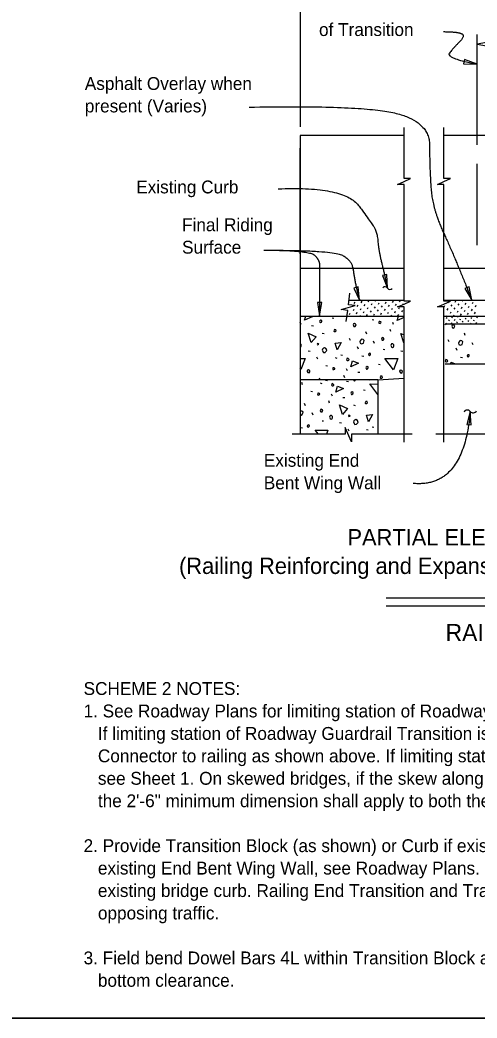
# Model space of a CAD drawing. Extents: x 0 to 41.1, y 0 to 26.
# Drawn here: x 20.53 to 27.71, y 0 to 15.65 of the extents above; entities that cross this region are included whole.
import ezdxf

# ---------------------------------------------------------------- set-up
doc = ezdxf.new("R2010")
doc.units = 0
for name, color, linetype in [('Dimension', 7, 'Continuous'), ('Miscellaneous', 7, 'Continuous'), ('Miscellaneous1', 7, 'Continuous'), ('TrafBarrierConc', 7, 'Continuous')]:
    doc.layers.add(name, color=color, linetype=linetype)

msp = doc.modelspace()

# ---------------------------------------------------------------- linework, layer by layer
at = {"layer": 'Dimension'}
for p, q in [((24.93, 19.167), (24.93, 13.975)), ((27.706, 13.69), (27.706, 15.42)), ((28.887, 6.585), (26.28, 6.585)), ((28.887, 6.46), (26.28, 6.46))]:
    msp.add_line(p, q, dxfattribs=at)
for points in [[(0, 0), (41.067, 0), (41.067, 25.97), (0, 25.97)], [(27.706, 15.271), (27.914, 15.236), (27.914, 15.307)], [(27.706, 14.955), (27.509, 15.031), (27.495, 14.962)], [(26.299, 11.446), (26.292, 11.657), (26.223, 11.643)], [(25.864, 11.257), (25.839, 11.467), (25.772, 11.447)], [(27.623, 11.259), (27.58, 11.466), (27.514, 11.44)], [(25.236, 11.012), (25.271, 11.22), (25.201, 11.22)], [(27.6, 9.513), (27.543, 9.309), (27.613, 9.302)]]:
    msp.add_lwpolyline(points, close=True, dxfattribs=at)
for points in [[(26.561, 12.221), (26.561, 13.073), (26.457, 13.073), (26.561, 13.118), (26.664, 13.163), (26.561, 13.163), (26.561, 13.966)], [(27.186, 12.221), (27.186, 13.073), (27.083, 13.073), (27.186, 13.118), (27.289, 13.163), (27.186, 13.163), (27.186, 13.966)], [(26.561, 9.028), (26.561, 11.151), (26.457, 11.151), (26.561, 11.196), (26.664, 11.241), (26.561, 11.241), (26.561, 12.221)], [(27.186, 9.028), (27.186, 11.151), (27.083, 11.151), (27.186, 11.196), (27.289, 11.241), (27.186, 11.241), (27.186, 12.221)], [(25.653, 10.922), (25.676, 11.096), (25.574, 11.109), (25.682, 11.14), (25.791, 11.171), (25.688, 11.185), (25.712, 11.367)], [(26.686, 9.153), (25.738, 9.153), (25.738, 9.037), (25.639, 9.262), (25.639, 9.153), (24.805, 9.153)], [(30.331, 9.153), (28.441, 9.153), (28.441, 9.037), (28.342, 9.262), (28.342, 9.153), (27.061, 9.153)]]:
    msp.add_lwpolyline(points, dxfattribs=at)
for centre, radius, start, end in [((26.261, 11.423), 0.0447, 31.1665, 142.8938), ((26.337, 11.469), 0.0447, 211.1665, 322.8938), ((27.554, 9.474), 0.0596, 40.6168, 152.344), ((27.645, 9.551), 0.0596, 220.6168, 332.344)]:
    msp.add_arc(centre, radius, start, end, dxfattribs=at)
for points in [[(27.178, 15.467), (27.387, 15.467), (27.531, 15.408), (27.322, 15.199), (27.218, 15.055), (27.706, 14.955)], [(24.131, 14.284), (25.927, 14.317), (26.961, 14.052), (26.961, 13.311), (27.008, 12.682), (27.371, 11.901), (27.623, 11.259)], [(24.585, 13.004), (25.616, 13.042), (26.064, 12.452), (26.14, 12.307), (26.163, 12.022), (26.292, 11.505), (26.299, 11.446)], [(24.362, 12.04), (25.371, 12.04), (25.744, 11.909), (25.788, 11.516), (25.864, 11.257)], [(24.362, 12.04), (25.079, 12.04), (25.236, 11.881), (25.236, 11.711), (25.236, 11.012)], [(27.6, 9.513), (27.496, 8.307), (26.703, 8.383)]]:
    msp.add_open_spline(points, degree=2, dxfattribs=at)
at = {"layer": 'Miscellaneous'}
for p, q in [((24.93, 11.982), (24.93, 13.642)), ((27.706, 12.121), (27.706, 13.395)), ((25.729, 11.252), (25.732, 11.258)), ((25.765, 11.093), (25.778, 11.115)), ((25.778, 11.204), (25.791, 11.226)), ((25.826, 11.155), (25.839, 11.177)), ((25.875, 11.106), (25.888, 11.128)), ((25.888, 11.217), (25.901, 11.239)), ((25.937, 11.168), (25.95, 11.19)), ((25.986, 11.119), (25.999, 11.141)), ((25.999, 11.229), (26.012, 11.252)), ((26.048, 11.181), (26.061, 11.203)), ((26.097, 11.132), (26.11, 11.154)), ((26.11, 11.242), (26.119, 11.258)), ((26.158, 11.194), (26.171, 11.216)), ((26.207, 11.145), (26.22, 11.167)), ((26.22, 11.255), (26.222, 11.258)), ((26.256, 11.096), (26.269, 11.118)), ((26.269, 11.207), (26.282, 11.229)), ((26.318, 11.158), (26.331, 11.18)), ((26.367, 11.109), (26.38, 11.131)), ((26.38, 11.22), (26.393, 11.242)), ((26.428, 11.171), (26.441, 11.193)), ((26.477, 11.122), (26.49, 11.144)), ((26.49, 11.233), (26.503, 11.255)), ((26.539, 11.184), (26.552, 11.206)), ((27.19, 11.151), (27.203, 11.173)), ((27.239, 11.102), (27.252, 11.124)), ((27.252, 11.213), (27.265, 11.235)), ((27.301, 11.164), (27.314, 11.186)), ((27.349, 11.115), (27.362, 11.137)), ((27.362, 11.226), (27.375, 11.248)), ((27.411, 11.177), (27.424, 11.199)), ((27.46, 11.128), (27.473, 11.15)), ((27.473, 11.239), (27.484, 11.258)), ((27.522, 11.19), (27.535, 11.212)), ((27.571, 11.141), (27.584, 11.163)), ((27.584, 11.252), (27.587, 11.258)), ((27.619, 11.092), (27.632, 11.114)), ((27.632, 11.203), (27.645, 11.225)), ((27.681, 11.154), (27.694, 11.176)), ((25.432, 10.98), (25.458, 10.974)), ((25.703, 11.031), (25.716, 11.054)), ((25.813, 11.044), (25.826, 11.066)), ((25.868, 11.005), (25.875, 11.018)), ((25.924, 11.057), (25.937, 11.079)), ((25.973, 11.008), (25.986, 11.031)), ((26.035, 11.07), (26.048, 11.092)), ((26.084, 11.021), (26.097, 11.044)), ((26.145, 11.083), (26.158, 11.105)), ((26.194, 11.034), (26.207, 11.057)), ((26.305, 11.047), (26.318, 11.07)), ((26.358, 11.005), (26.367, 11.021)), ((26.415, 11.06), (26.428, 11.082)), ((26.464, 11.011), (26.477, 11.034)), ((26.526, 11.073), (26.539, 11.095)), ((27.225, 10.969), (27.235, 10.986)), ((27.234, 11.005), (27.239, 11.014)), ((27.288, 11.053), (27.301, 11.076)), ((27.312, 10.979), (27.322, 10.996)), ((27.337, 11.005), (27.349, 11.027)), ((27.351, 10.94), (27.361, 10.957)), ((27.398, 11.066), (27.411, 11.089)), ((27.4, 10.989), (27.41, 11.005)), ((27.439, 10.95), (27.448, 10.966)), ((27.447, 11.017), (27.46, 11.04)), ((27.487, 10.998), (27.493, 11.008)), ((27.509, 11.079), (27.522, 11.101)), ((27.526, 10.959), (27.536, 10.976)), ((27.558, 11.03), (27.571, 11.053)), ((27.614, 10.969), (27.624, 10.986)), ((27.668, 11.043), (27.681, 11.066)), ((27.701, 10.979), (27.711, 10.996)), ((24.944, 10.877), (24.932, 10.911)), ((25.108, 10.858), (25.14, 10.854)), ((26.058, 10.955), (26.084, 10.95)), ((26.355, 10.764), (26.341, 10.799)), ((26.397, 10.874), (26.385, 10.907)), ((27.216, 10.883), (27.225, 10.898)), ((27.264, 10.93), (27.273, 10.947)), ((27.303, 10.891), (27.312, 10.908)), ((27.39, 10.901), (27.4, 10.918)), ((27.478, 10.911), (27.487, 10.928)), ((27.523, 10.883), (27.526, 10.889)), ((27.565, 10.92), (27.575, 10.937)), ((27.605, 10.883), (27.614, 10.898)), ((27.653, 10.93), (27.662, 10.947)), ((27.692, 10.891), (27.701, 10.908)), ((25.276, 10.739), (25.305, 10.732)), ((25.718, 10.623), (25.704, 10.658)), ((25.975, 10.723), (25.96, 10.759)), ((27.522, 10.702), (27.508, 10.737)), ((25.844, 10.49), (25.831, 10.524)), ((26.097, 10.577), (26.082, 10.612)), ((26.234, 10.488), (26.259, 10.485)), ((27.266, 10.601), (27.252, 10.636)), ((27.392, 10.468), (27.379, 10.502)), ((27.644, 10.555), (27.63, 10.59)), ((25.057, 10.464), (25.087, 10.458)), ((25.206, 10.329), (25.193, 10.363)), ((25.48, 10.356), (25.508, 10.349)), ((25.566, 10.4), (25.595, 10.393)), ((25.897, 10.384), (25.927, 10.379)), ((26.51, 10.46), (26.54, 10.455)), ((27.445, 10.362), (27.475, 10.357)), ((25.333, 10.23), (25.359, 10.225)), ((25.672, 10.149), (25.66, 10.182)), ((26.16, 10.251), (26.187, 10.246)), ((25.246, 10.008), (25.236, 10.034)), ((25.63, 10.039), (25.616, 10.075)), ((25.837, 10.129), (25.869, 10.126)), ((24.969, 9.931), (24.957, 9.965)), ((25.243, 9.958), (25.271, 9.95)), ((25.33, 10.002), (25.358, 9.995)), ((25.66, 9.986), (25.69, 9.981)), ((26.005, 10.011), (26.017, 10.008)), ((25.096, 9.832), (25.123, 9.827)), ((25.436, 9.751), (25.423, 9.784)), ((25.6, 9.731), (25.632, 9.728)), ((25.924, 9.853), (25.95, 9.848)), ((25.013, 9.6), (24.999, 9.636)), ((25.393, 9.641), (25.379, 9.676)), ((25.768, 9.613), (25.796, 9.606)), ((25.135, 9.454), (25.121, 9.489)), ((24.935, 9.261), (24.965, 9.256)), ((25.273, 9.365), (25.298, 9.362)), ((25.549, 9.337), (25.579, 9.332)), ((25.697, 9.203), (25.685, 9.236)), ((26.058, 9.273), (26.086, 9.266)), ((25.971, 9.229), (26, 9.222))]:
    msp.add_line(p, q, dxfattribs=at)
for points in [[(24.997, 10.941), (25.018, 11.008)], [(25.088, 11.008), (25.119, 10.996), (24.997, 10.941)], [(26.45, 10.937), (26.472, 11.008)], [(26.561, 10.987), (26.45, 10.937)], [(26.532, 11.008), (26.561, 10.997)], [(25.245, 10.905), (25.252, 10.905), (25.266, 10.913), (25.271, 10.928), (25.269, 10.937), (25.255, 10.944), (25.237, 10.934), (25.234, 10.923), (25.237, 10.913), (25.245, 10.905)], [(25.766, 10.861), (25.775, 10.845), (25.796, 10.842), (25.805, 10.858), (25.808, 10.872), (25.8, 10.881), (25.784, 10.89), (25.768, 10.884), (25.762, 10.868), (25.766, 10.861)], [(26.166, 10.897), (26.185, 10.891), (26.197, 10.9), (26.199, 10.913), (26.196, 10.916), (26.181, 10.923), (26.169, 10.921), (26.167, 10.909), (26.166, 10.897)], [(27.215, 10.871), (27.206, 10.883)], [(27.219, 10.883), (27.215, 10.871)], [(27.314, 10.84), (27.323, 10.824), (27.344, 10.82), (27.353, 10.836), (27.356, 10.85), (27.347, 10.859), (27.332, 10.868), (27.316, 10.863), (27.31, 10.847), (27.314, 10.84)], [(25.105, 10.593), (25.057, 10.739), (25.183, 10.684), (25.105, 10.593)], [(25.464, 10.764), (25.485, 10.764), (25.496, 10.775), (25.49, 10.794), (25.467, 10.796), (25.464, 10.785), (25.458, 10.776), (25.464, 10.764), (25.46, 10.768)], [(25.872, 10.585), (25.895, 10.573), (25.925, 10.585), (25.937, 10.623), (25.92, 10.64), (25.897, 10.646), (25.886, 10.639), (25.874, 10.619), (25.865, 10.603), (25.872, 10.585)], [(26.206, 10.644), (26.215, 10.628), (26.234, 10.63), (26.243, 10.642), (26.245, 10.662), (26.233, 10.667), (26.224, 10.669), (26.213, 10.665), (26.21, 10.662), (26.206, 10.644)], [(26.558, 10.589), (26.51, 10.736), (26.561, 10.714)], [(24.93, 10.519), (24.94, 10.527), (24.948, 10.538), (24.948, 10.559), (24.932, 10.575), (24.93, 10.575)], [(25.204, 10.557), (25.223, 10.566), (25.216, 10.573), (25.204, 10.578), (25.199, 10.566), (25.204, 10.557)], [(25.275, 10.472), (25.298, 10.435), (25.321, 10.437), (25.329, 10.446), (25.349, 10.465), (25.336, 10.495), (25.312, 10.509), (25.294, 10.502), (25.28, 10.488), (25.275, 10.472)], [(25.511, 10.476), (25.478, 10.58), (25.572, 10.593), (25.511, 10.476)], [(26.351, 10.545), (26.362, 10.524), (26.379, 10.513), (26.394, 10.524), (26.401, 10.534), (26.401, 10.555), (26.385, 10.571), (26.365, 10.57), (26.356, 10.561), (26.351, 10.545)], [(26.561, 10.593), (26.558, 10.589)], [(27.42, 10.564), (27.443, 10.551), (27.473, 10.564), (27.485, 10.601), (27.468, 10.619), (27.445, 10.624), (27.434, 10.617), (27.422, 10.597), (27.413, 10.581), (27.42, 10.564)], [(24.93, 10.344), (25.008, 10.343), (24.942, 10.168)], [(25.669, 10.311), (25.681, 10.31), (25.694, 10.315), (25.697, 10.326), (25.692, 10.334), (25.681, 10.342), (25.669, 10.347), (25.662, 10.333), (25.658, 10.322), (25.669, 10.311)], [(26.008, 10.396), (26.019, 10.386), (26.029, 10.393), (26.036, 10.403), (26.033, 10.421), (26.024, 10.423), (26.012, 10.421), (26.001, 10.41), (26.008, 10.396)], [(26.395, 10.165), (26.261, 10.342), (26.461, 10.34), (26.395, 10.165)], [(27.556, 10.375), (27.567, 10.364), (27.577, 10.371), (27.584, 10.382), (27.581, 10.399), (27.572, 10.401), (27.56, 10.399), (27.549, 10.389), (27.556, 10.375)], [(24.942, 10.168), (24.93, 10.185)], [(25.441, 10.172), (25.46, 10.167), (25.473, 10.175), (25.474, 10.188), (25.471, 10.191), (25.457, 10.198), (25.444, 10.197), (25.443, 10.184), (25.441, 10.172)], [(25.725, 10.212), (25.754, 10.304), (25.847, 10.267), (25.725, 10.212)], [(25.973, 10.177), (25.98, 10.177), (25.994, 10.184), (25.999, 10.2), (25.998, 10.209), (25.983, 10.216), (25.966, 10.205), (25.962, 10.195), (25.966, 10.184), (25.973, 10.177)], [(27.217, 10.29), (27.229, 10.288), (27.241, 10.293), (27.245, 10.304), (27.24, 10.313), (27.229, 10.32), (27.217, 10.325), (27.21, 10.311), (27.206, 10.3)], [(27.206, 10.3), (27.217, 10.29)], [(27.294, 10.258), (27.301, 10.283), (27.364, 10.258)], [(25.041, 10.136), (25.05, 10.121), (25.071, 10.117), (25.08, 10.133), (25.084, 10.147), (25.075, 10.156), (25.059, 10.165), (25.043, 10.159), (25.038, 10.144), (25.041, 10.136)], [(26.192, 10.036), (26.213, 10.036), (26.224, 10.046), (26.219, 10.066), (26.196, 10.068), (26.192, 10.057), (26.187, 10.048), (26.192, 10.036), (26.189, 10.039)], [(26.494, 10.133), (26.503, 10.117), (26.524, 10.113), (26.533, 10.129), (26.537, 10.144), (26.528, 10.152), (26.512, 10.161), (26.496, 10.156), (26.491, 10.14), (26.494, 10.133)], [(25.432, 9.913), (25.445, 9.912), (25.457, 9.917), (25.46, 9.928), (25.455, 9.936), (25.445, 9.943), (25.432, 9.949), (25.425, 9.935), (25.422, 9.924), (25.432, 9.913)], [(25.489, 9.814), (25.517, 9.906), (25.611, 9.869), (25.489, 9.814)], [(25.767, 10.008), (25.772, 9.998)], [(25.772, 9.998), (25.782, 9.988), (25.793, 9.995), (25.8, 10.005), (25.799, 10.008)], [(25.786, 10.008), (25.785, 10.011), (25.792, 10.008)], [(26.15, 9.778), (26.024, 9.943), (26.15, 9.942)], [(25.204, 9.774), (25.224, 9.768), (25.236, 9.777), (25.238, 9.79), (25.234, 9.793), (25.22, 9.8), (25.208, 9.798), (25.206, 9.786), (25.204, 9.774)], [(25.736, 9.779), (25.743, 9.779), (25.757, 9.786), (25.763, 9.802), (25.761, 9.811), (25.747, 9.818), (25.729, 9.807), (25.726, 9.797), (25.729, 9.786), (25.736, 9.779)], [(25.597, 9.466), (25.549, 9.613), (25.674, 9.558), (25.597, 9.466)], [(25.955, 9.638), (25.977, 9.638), (25.987, 9.648), (25.982, 9.668), (25.959, 9.669), (25.955, 9.659), (25.95, 9.65), (25.955, 9.638), (25.952, 9.641)], [(24.93, 9.452), (24.934, 9.45), (24.964, 9.463), (24.976, 9.5), (24.958, 9.517), (24.935, 9.523), (24.93, 9.519)], [(25.245, 9.521), (25.254, 9.505), (25.273, 9.507), (25.282, 9.519), (25.284, 9.539), (25.271, 9.544), (25.262, 9.546), (25.252, 9.542), (25.248, 9.539), (25.245, 9.521)], [(25.39, 9.422), (25.4, 9.401), (25.418, 9.39), (25.432, 9.401), (25.439, 9.411), (25.439, 9.433), (25.423, 9.448), (25.404, 9.447), (25.395, 9.438), (25.39, 9.422)], [(25.696, 9.431), (25.715, 9.44), (25.708, 9.447), (25.696, 9.452), (25.69, 9.44), (25.696, 9.431)], [(26.003, 9.349), (25.97, 9.454), (26.063, 9.466), (26.003, 9.349)], [(25.047, 9.273), (25.057, 9.263), (25.068, 9.27), (25.075, 9.281), (25.072, 9.298), (25.063, 9.3), (25.05, 9.298), (25.04, 9.288), (25.047, 9.273)], [(25.766, 9.346), (25.789, 9.309), (25.812, 9.311), (25.821, 9.319), (25.84, 9.339), (25.828, 9.369), (25.803, 9.383), (25.786, 9.376), (25.772, 9.362), (25.766, 9.346)], [(25.216, 9.153), (25.167, 9.219), (25.366, 9.217), (25.343, 9.153)]]:
    msp.add_lwpolyline(points, dxfattribs=at)
at = {"layer": 'Miscellaneous1'}
msp.add_lwpolyline([(0, 25.97), (41.067, 25.97), (41.067, 0), (0, 0)], close=True, dxfattribs=at)
at = {"layer": 'TrafBarrierConc'}
for p, q in [((24.93, 13.841), (24.93, 11.758)), ((26.561, 13.841), (24.93, 13.841)), ((28.873, 13.841), (27.186, 13.841)), ((24.93, 11.758), (24.93, 9.153)), ((24.93, 11.758), (26.561, 11.758)), ((27.186, 11.758), (33.206, 11.758)), ((25.698, 11.258), (26.561, 11.258)), ((27.186, 11.258), (27.967, 11.258)), ((24.93, 11.008), (26.561, 11.008)), ((27.186, 11.008), (29.745, 11.008)), ((27.206, 10.883), (29.686, 10.883)), ((27.206, 10.258), (35.044, 10.258)), ((26.15, 10.008), (26.562, 10.034)), ((26.15, 10.008), (24.93, 10.008)), ((26.15, 10.008), (26.15, 9.153))]:
    msp.add_line(p, q, dxfattribs=at)

# ---------------------------------------------------------------- texts
at = {"layer": 'Dimension'}
for s, height, p in [('of Transition', 0.2016, (25.226, 15.399)), ('Asphalt Overlay when ', 0.2016, (21.551, 14.553)), ('present (Varies)', 0.2016, (21.551, 14.201)), ('Existing Curb', 0.2016, (22.358, 12.931)), ('Final Riding ', 0.2016, (23.077, 12.338)), ('Surface', 0.2016, (23.077, 11.986)), ('Existing End ', 0.2016, (24.36, 8.644)), ('Bent Wing Wall', 0.2016, (24.36, 8.292)), ('PARTIAL ELEVATION OF INSIDE FACE OF RAILING', 0.256, (25.673, 7.411)), ('(Railing Reinforcing and Expansion Dowel Assemblies not shown for clarity)', 0.256, (23.03, 6.963)), ('RAILING END TREATMENT FOR ', 0.2688, (27.212, 5.911)), ('SCHEME 2 NOTES:', 0.2016, (21.532, 5.066)), ('1. See Roadway Plans for limiting station of Roadway Guardrail Transition or other site specific treatment.  ', 0.2016, (21.532, 4.714)), ('   If limiting station of Roadway Guardrail Transition is along the Wing Wall, attach Thrie-Beam Terminal ', 0.2016, (21.532, 4.362)), ('   Connector to railing as shown above. If limiting station of Roadway Guardrail Transition is on the bridge, ', 0.2016, (21.532, 4.01)), ('   see Sheet 1. On skewed bridges, if the skew along the deck joint extends across the width of the railing, ', 0.2016, (21.532, 3.658)), ('   the 2\'-6" minimum dimension shall apply to both the front and back face of the railing.', 0.2016, (21.532, 3.306)), ('2. Provide Transition Block (as shown) or Curb if existing Approach Slab Curb does not extend beyond end of ', 0.2016, (21.532, 2.602)), ('   existing End Bent Wing Wall, see Roadway Plans. Shape and height of Transition Block or Curb shall match ', 0.2016, (21.532, 2.25)), ('   existing bridge curb. Railing End Transition and Transition Block may be omitted on trailing ends with no ', 0.2016, (21.532, 1.898)), ('   opposing traffic.', 0.2016, (21.532, 1.546)), ('3. Field bend Dowel Bars 4L within Transition Block as required to maintain 2" top and side clearance and 3" ', 0.2016, (21.532, 0.842)), ('   bottom clearance.', 0.2016, (21.532, 0.49))]:
    msp.add_text(s, height=height, dxfattribs=at).set_placement(p)

doc.saveas('drawing.dxf')
